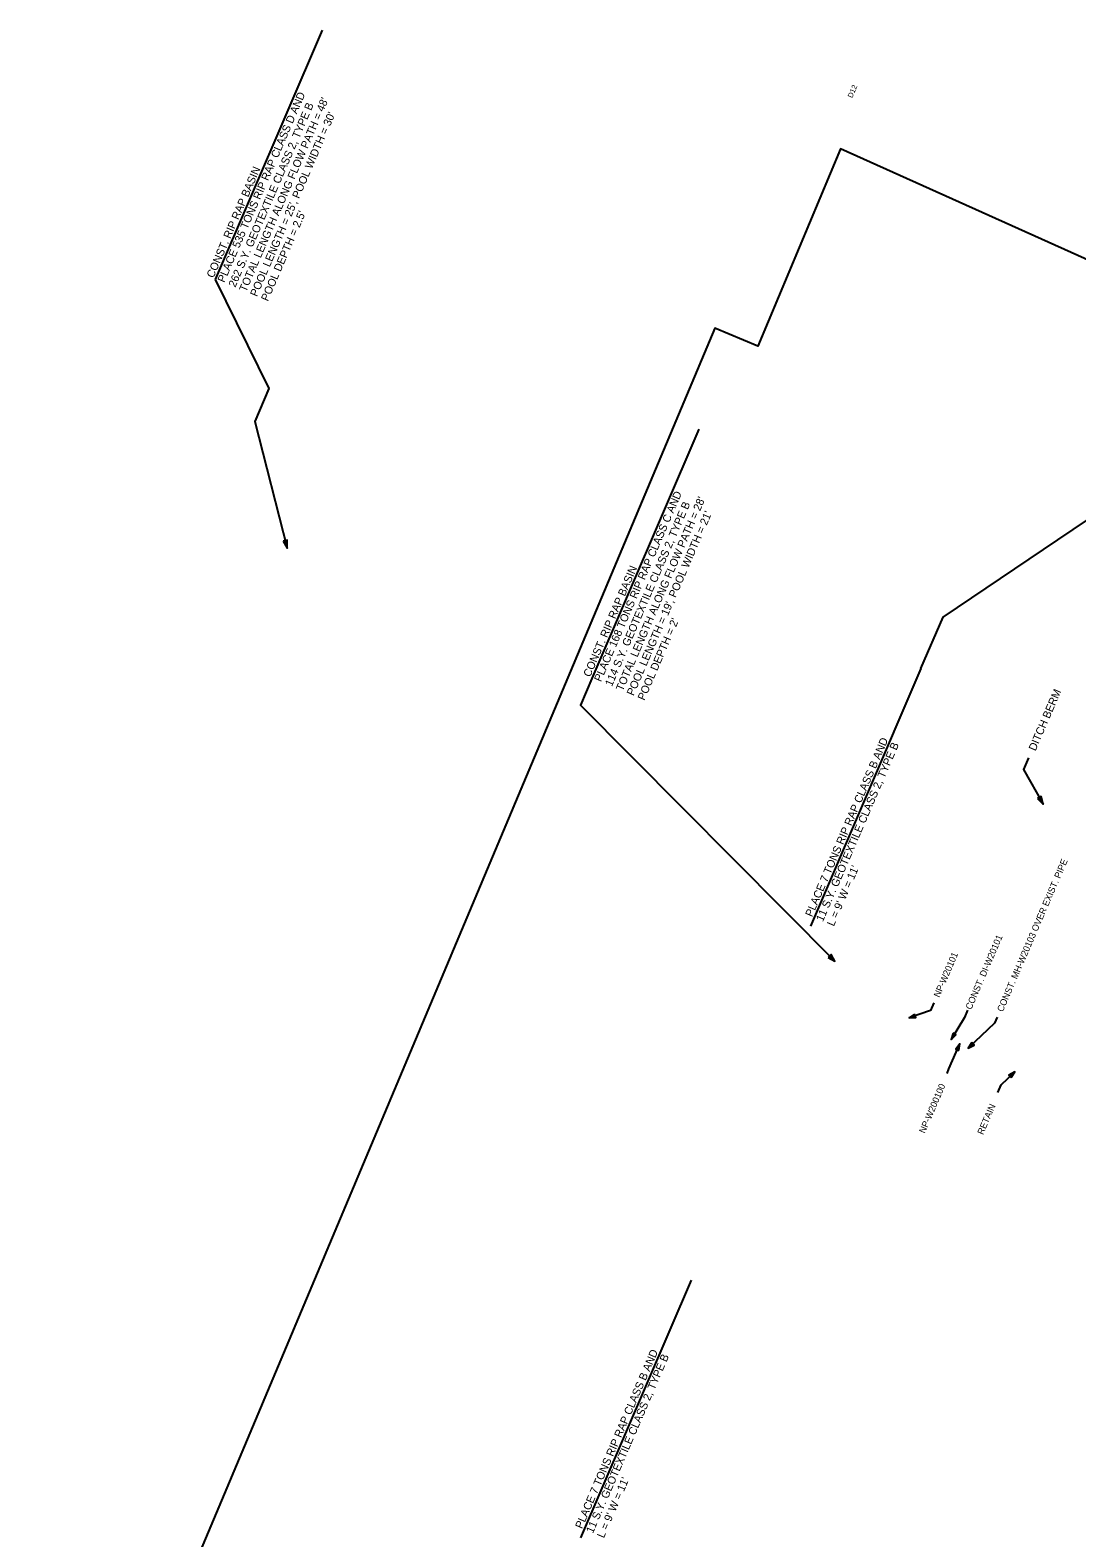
# Model space of a CAD drawing. Extents: x 1615213 to 1616738, y 1098243 to 1100099.
# Drawn here: x 1615213 to 1616009, y 1098952 to 1100099 of the extents above; entities that cross this region are included whole.
import ezdxf

# ---------------------------------------------------------------- set-up
doc = ezdxf.new("R2010")
doc.units = 0
for name, color, linetype in [('Plan_Clip', 7, 'Continuous'), ('RD_SHT_Bndy', 7, 'Continuous'), ('RD_TX_Drainage', 7, 'Continuous')]:
    doc.layers.add(name, color=color, linetype=linetype)

msp = doc.modelspace()

# ---------------------------------------------------------------- linework, layer by layer
at = {"layer": 'Plan_Clip'}
msp.add_lwpolyline([(1615502.7, 1098507.9), (1615778.5, 1098389.7), (1616070.1, 1098243.5), (1616662.9, 1099630.3), (1616368.7, 1099765.8), (1616095.1, 1099888.9), (1615829.5, 1100008.4), (1615766.4, 1099858.4), (1615733.7, 1099872.1), (1615213.1, 1098634.6)], close=True, dxfattribs=at)
msp.add_lwpolyline([(1615502.7, 1098507.9), (1615778.5, 1098389.7), (1616070.1, 1098243.5), (1616662.9, 1099630.3), (1616368.7, 1099765.8), (1616095.1, 1099888.9), (1615829.5, 1100008.4), (1615766.4, 1099858.4), (1615733.7, 1099872.1), (1615213.1, 1098634.6)], close=True, dxfattribs=at)
msp.add_lwpolyline([(1615502.7, 1098507.9), (1615778.5, 1098389.7), (1616070.1, 1098243.5), (1616662.9, 1099630.3), (1616368.7, 1099765.8), (1616095.1, 1099888.9), (1615829.5, 1100008.4), (1615766.4, 1099858.4), (1615733.7, 1099872.1), (1615213.1, 1098634.6)], close=True, dxfattribs=at)
msp.add_lwpolyline([(1615502.7, 1098507.9), (1615778.5, 1098389.7), (1616070.1, 1098243.5), (1616662.9, 1099630.3), (1616368.7, 1099765.8), (1616095.1, 1099888.9), (1615829.5, 1100008.4), (1615766.4, 1099858.4), (1615733.7, 1099872.1), (1615213.1, 1098634.6)], close=True, dxfattribs=at)
msp.add_lwpolyline([(1615502.7, 1098507.9), (1615778.5, 1098389.7), (1616070.1, 1098243.5), (1616662.9, 1099630.3), (1616368.7, 1099765.8), (1616095.1, 1099888.9), (1615829.5, 1100008.4), (1615766.4, 1099858.4), (1615733.7, 1099872.1), (1615213.1, 1098634.6)], close=True, dxfattribs=at)
msp.add_lwpolyline([(1615502.7, 1098507.9), (1615778.5, 1098389.7), (1616070.1, 1098243.5), (1616662.9, 1099630.3), (1616368.7, 1099765.8), (1616095.1, 1099888.9), (1615829.5, 1100008.4), (1615766.4, 1099858.4), (1615733.7, 1099872.1), (1615213.1, 1098634.6)], close=True, dxfattribs=at)
at = {"layer": 'RD_TX_Drainage'}
for p, q in [((1615435.2, 1100098.6), (1615353.9, 1099909.1)), ((1615721.6, 1099795.1), (1615640.3, 1099605.6)), ((1615890.6, 1099613.1), (1615806.6, 1099417.3)), ((1615715.7, 1099147.9), (1615631.7, 1098952))]:
    msp.add_line(p, q, dxfattribs=at)
for points in [[(1615353.9, 1099909.1), (1615394.7, 1099826.2), (1615383.9, 1099801.1), (1615408.5, 1099704.8)], [(1615890.6, 1099613.1), (1615907.4, 1099652.1), (1616093.6, 1099777.7)], [(1615640.3, 1099605.6), (1615631.7, 1099585.4), (1615825.2, 1099390.5)], [(1615972.4, 1099545.2), (1615968.6, 1099536.3), (1615983.5, 1099509.9)], [(1615900.3, 1099358.9), (1615897.8, 1099353.1), (1615881.6, 1099347.4)], [(1615926.1, 1099353.4), (1615923.7, 1099347.8), (1615913.6, 1099331)], [(1615948.6, 1099348), (1615946.6, 1099343.5), (1615926.6, 1099324.4)], [(1615910.5, 1099305.2), (1615911.9, 1099308.6), (1615920.2, 1099327.7)], [(1615949.1, 1099290.8), (1615951.5, 1099296.5), (1615961.9, 1099306.4)]]:
    msp.add_lwpolyline(points, dxfattribs=at)
for points in [[(1615405.5, 1099710), (1615408.5, 1099704.8), (1615408.5, 1099710.8)], [(1615979.3, 1099514.2), (1615983.5, 1099509.9), (1615982, 1099515.7)], [(1615820, 1099393.5), (1615825.2, 1099390.5), (1615822.2, 1099395.7)], [(1615885.7, 1099350.2), (1615881.6, 1099347.4), (1615886.6, 1099347.8)], [(1615915, 1099335.8), (1615913.6, 1099331), (1615917.2, 1099334.5)], [(1615919.4, 1099322.7), (1615920.2, 1099327.7), (1615917.1, 1099323.7)], [(1615929.2, 1099328.7), (1615926.6, 1099324.4), (1615931, 1099326.8)], [(1615959.3, 1099302.2), (1615961.9, 1099306.4), (1615957.5, 1099304)]]:
    msp.add_lwpolyline(points, close=True, dxfattribs=at)

# ---------------------------------------------------------------- texts
at = {"layer": 'RD_SHT_Bndy'}
msp.add_text('D12', height=4, rotation=66.7846, dxfattribs=at).set_placement((1615838.3, 1100046.7))
at = {"layer": 'RD_TX_Drainage'}
for s, height, p in [('PLACE 535 TONS RIP RAP CLASS D AND', 6, (1615360.8, 1099906.2)), ('262 S.Y. GEOTEXTILE CLASS 2, TYPE B', 6, (1615369.1, 1099902.6)), ("TOTAL LENGTH ALONG FLOW PATH = 48'", 6, (1615377.3, 1099899.1)), ("POOL LENGTH = 25', POOL WIDTH = 30'", 6, (1615385.6, 1099895.5)), ('CONST. RIP RAP BASIN', 6, (1615352.5, 1099909.7)), ("POOL DEPTH = 2.5'", 6, (1615393.9, 1099892)), ('PLACE 168 TONS RIP RAP CLASS C AND', 6, (1615647.2, 1099602.6)), ('114 S.Y. GEOTEXTILE CLASS 2, TYPE B', 6, (1615655.5, 1099599.1)), ("TOTAL LENGTH ALONG FLOW PATH = 28'", 6, (1615663.8, 1099595.5)), ("POOL LENGTH = 19', POOL WIDTH = 21'", 6, (1615672, 1099592)), ('CONST. RIP RAP BASIN', 6, (1615639, 1099606.2)), ("POOL DEPTH = 2'", 6, (1615680.3, 1099588.4)), ('DITCH BERM', 6, (1615977.7, 1099550)), ('PLACE 7 TONS RIP RAP CLASS B AND', 6, (1615807.8, 1099423.8)), ('11 S.Y. GEOTEXTILE CLASS 2, TYPE B', 6, (1615816, 1099420.2)), ("L = 9' W = 11'", 6, (1615824.3, 1099416.7)), ('CONST. MH-W20103 OVER EXIST. PIPE', 5, (1615952.8, 1099351.6)), ('CONST. DI-W20101', 5, (1615928.8, 1099353.3)), ('NP-W20101', 5, (1615904.6, 1099362.6)), ('NP-W200100', 5, (1615893.5, 1099259.2)), ('RETAIN', 5, (1615937.8, 1099258.2)), ('PLACE 7 TONS RIP RAP CLASS B AND', 6, (1615632.8, 1098958.5)), ('11 S.Y. GEOTEXTILE CLASS 2, TYPE B', 6, (1615641.1, 1098955)), ("L = 9' W = 11'", 6, (1615649.4, 1098951.4))]:
    msp.add_text(s, height=height, rotation=66.7846, dxfattribs=at).set_placement(p)

doc.saveas('drawing.dxf')
